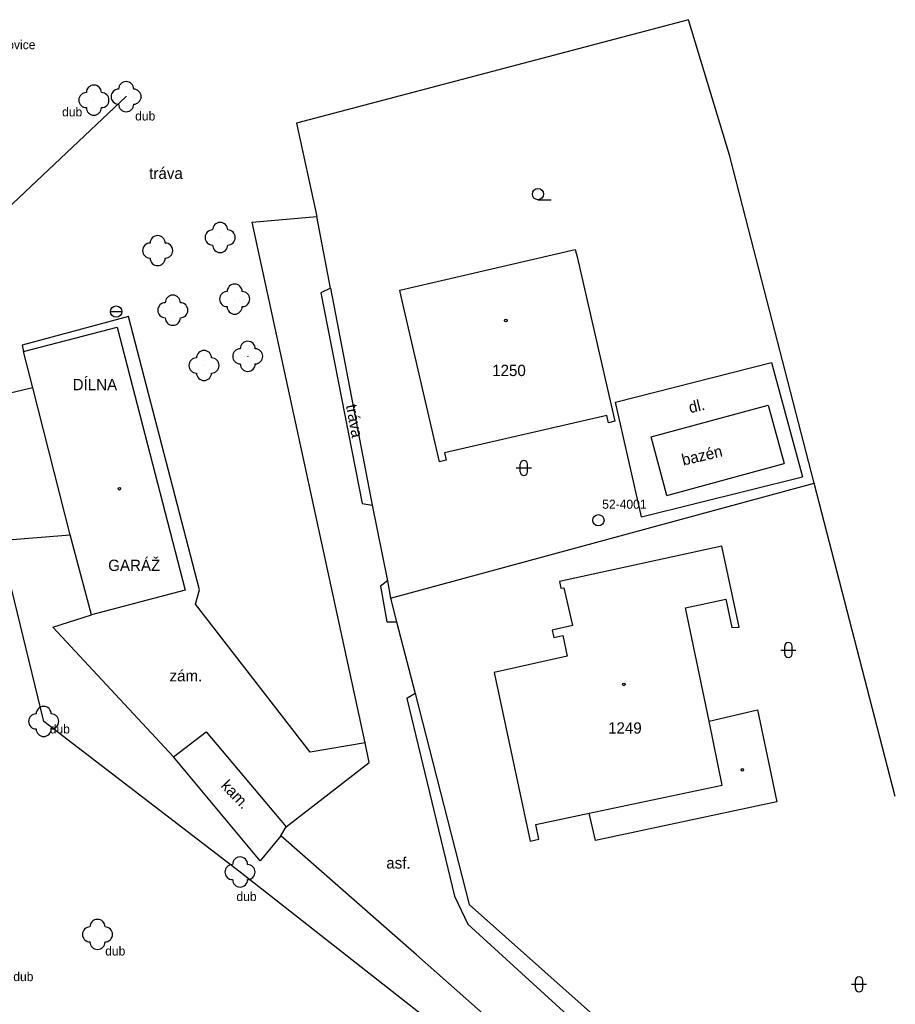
# Model space of a CAD drawing. Extents: x -794191 to -788944, y -1117087 to -1105044.
# Drawn here: x -792191 to -792132.8, y -1110967.2 to -1110901.8 of the extents above; entities that cross this region are included whole.
import ezdxf

# ---------------------------------------------------------------- set-up
doc = ezdxf.new("R2010")
doc.units = 0
for name, color, linetype in [('Doplněk polohopisu', 7, 'Continuous'), ('Doplňkové značky', 7, 'Continuous'), ('Hranice - ploty_ zdi', 7, 'Continuous'), ('Komunikace', 7, 'Continuous'), ('Pomocné popisy', 7, 'Continuous'), ('Popisy budov', 7, 'Continuous'), ('Stavební objekty', 7, 'Continuous'), ('temporary_level_1', 7, 'Continuous'), ('Zeleň', 7, 'Continuous'), ('Značky druhů budov', 7, 'Continuous'), ('Značky druhů pozemků', 7, 'Continuous'), ('Čísla popisná', 7, 'Continuous')]:
    doc.layers.add(name, color=color, linetype=linetype)

msp = doc.modelspace()

# ---------------------------------------------------------------- linework, layer by layer
at = {"layer": 'Doplněk polohopisu'}
for points in [[(-792168.03, -1110949.86), (-792171.67, -1110950.47), (-792179.29, -1110940.65), (-792179.02, -1110939.7), (-792183.73, -1110921.55), (-792190.8, -1110923.44), (-792190.7, -1110923.87)], [(-792173.62, -1110956.03), (-792174.99, -1110957.68), (-792180.75, -1110950.77), (-792188.75, -1110942.17), (-792186.18, -1110941.36)], [(-792180.75, -1110950.77), (-792178.58, -1110949.12), (-792173.27, -1110955.42)]]:
    msp.add_lwpolyline(points, dxfattribs=at)
at = {"layer": 'Doplňkové značky'}
msp.add_line((-792184.926, -1110921.22), (-792184.174, -1110921.22), dxfattribs=at)
msp.add_circle((-792184.55, -1110921.22), 0.375, dxfattribs=at)
at = {"layer": 'Hranice - ploty_ zdi'}
for p, q in [((-792146.58, -1110901.84), (-792172.59, -1110908.71)), ((-792172.59, -1110908.71), (-792171.23, -1110914.91)), ((-792170.32, -1110919.67), (-792171.23, -1110914.91)), ((-792170.32, -1110919.67), (-792167.56, -1110934.07)), ((-792141.29, -1110927.43), (-792140.23, -1110931.31)), ((-792148.01, -1110933.42), (-792140.23, -1110931.31)), ((-792149.69, -1110934.84), (-792139.01, -1110932.18)), ((-792166.35, -1110940.24), (-792138.23, -1110932.6)), ((-792132.85, -1110953.41), (-792138.23, -1110932.6)), ((-792167.56, -1110934.07), (-792166.55, -1110939.1)), ((-792165.94, -1110941.81), (-792164.72, -1110946.58))]:
    msp.add_line(p, q, dxfattribs=at)
for points in [[(-792138.23, -1110932.6), (-792142.77, -1110915.05), (-792143.84, -1110910.9), (-792146.58, -1110901.84)], [(-792149.69, -1110934.84), (-792151.41, -1110927.24), (-792141.07, -1110924.6), (-792139.01, -1110932.18)], [(-792190.08, -1110926.29), (-792195.76, -1110927.61), (-792192.29, -1110936.41), (-792187.61, -1110936.03)], [(-792148.01, -1110933.42), (-792149.06, -1110929.53), (-792141.29, -1110927.43)], [(-792166.55, -1110939.1), (-792166.35, -1110940.24), (-792165.94, -1110941.81)], [(-792164.72, -1110946.58), (-792161.13, -1110960.59), (-792138.64, -1110980.62)]]:
    msp.add_lwpolyline(points, dxfattribs=at)
at = {"layer": 'Komunikace'}
for p, q in [((-792164.62, -1110963.92), (-792173.62, -1110956.03)), ((-792144.04, -1110982.14), (-792164.62, -1110963.92))]:
    msp.add_line(p, q, dxfattribs=at)
for points in [[(-792168.03, -1110949.86), (-792175.53, -1110915.29), (-792171.23, -1110914.91)], [(-792170.32, -1110919.67), (-792170.96, -1110919.98), (-792168.22, -1110933.97), (-792167.56, -1110934.07)], [(-792166.55, -1110939.1), (-792167.02, -1110939.44), (-792166.58, -1110941.81), (-792165.94, -1110941.81)], [(-792164.72, -1110946.58), (-792165.27, -1110946.9), (-792162.1, -1110960.02), (-792161.21, -1110961.88), (-792139.87, -1110981.39), (-792136.93, -1110983.32), (-792133.45, -1110983.35)], [(-792173.62, -1110956.03), (-792173.27, -1110955.42), (-792167.77, -1110951.15), (-792168.03, -1110949.86)]]:
    msp.add_lwpolyline(points, dxfattribs=at)
at = {"layer": 'Stavební objekty'}
for p, q in [((-792190.7, -1110923.87), (-792184.49, -1110922.25)), ((-792184.49, -1110922.25), (-792179.98, -1110939.71)), ((-792186.18, -1110941.36), (-792187.61, -1110936.03)), ((-792179.98, -1110939.71), (-792186.18, -1110941.36))]:
    msp.add_line(p, q, dxfattribs=at)
for points in [[(-792162.77, -1110930.6), (-792162.66, -1110931.09), (-792163.09, -1110931.19), (-792165.64, -1110920.21), (-792165.73, -1110919.79), (-792154.09, -1110917.09), (-792153.97, -1110917.58), (-792151.46, -1110928.5)], [(-792187.61, -1110936.03), (-792190.08, -1110926.29), (-792190.7, -1110923.87)], [(-792151.46, -1110928.5), (-792151.89, -1110928.6), (-792152, -1110928.11), (-792162.77, -1110930.6)], [(-792144.35, -1110936.8), (-792155.13, -1110939.15), (-792155.04, -1110939.59), (-792154.84, -1110939.55), (-792154.28, -1110942.07), (-792155.62, -1110942.37), (-792155.51, -1110942.86), (-792154.92, -1110942.73), (-792154.62, -1110944.09), (-792159.47, -1110945.17), (-792157.09, -1110956.37), (-792156.51, -1110956.25), (-792156.71, -1110955.28), (-792153.16, -1110954.53), (-792144.33, -1110952.65), (-792145.21, -1110948.42), (-792146.78, -1110940.89)], [(-792146.78, -1110940.89), (-792144.1, -1110940.31), (-792143.69, -1110942.2), (-792143.21, -1110942.17), (-792144.35, -1110936.8)], [(-792145.21, -1110948.42), (-792141.99, -1110947.66), (-792140.71, -1110953.76), (-792152.74, -1110956.33), (-792153.16, -1110954.53)]]:
    msp.add_lwpolyline(points, dxfattribs=at)
at = {"layer": 'temporary_level_1'}
for radius in [0.375, 0.0005]:
    msp.add_circle((-792152.55, -1110935.07), radius, dxfattribs=at)
at = {"layer": 'Zeleň'}
for points in [[(-792195.76, -1110927.61), (-792194.2, -1110916.65), (-792183.89, -1110906.95)], [(-792147, -1110981.48), (-792176.33, -1110958.43), (-792189.36, -1110948.43), (-792192.29, -1110936.41)]]:
    msp.add_lwpolyline(points, dxfattribs=at)
for centre in [(-792186.03, -1110907.18), (-792183.89, -1110906.95), (-792177.65, -1110916.3), (-792181.8, -1110917.17), (-792176.69, -1110920.39), (-792180.79, -1110921.13), (-792175.82, -1110924.19), (-792178.72, -1110924.8), (-792189.36, -1110948.43), (-792176.33, -1110958.43), (-792185.79, -1110962.57)]:
    msp.add_circle(centre, 0.0005, dxfattribs=at)
for centre, start, end in [((-792186.03, -1110906.68), 0, 179.99999), ((-792183.89, -1110906.45), 0, 179.99999), ((-792186.53, -1110907.18), 89.99999, 269.99999), ((-792185.53, -1110907.18), 270, 89.99999), ((-792184.39, -1110906.95), 89.99999, 269.99999), ((-792183.39, -1110906.95), 270, 89.99999), ((-792183.89, -1110907.45), 179.99999, 359.99999), ((-792186.03, -1110907.68), 179.99999, 359.99999), ((-792177.65, -1110915.8), 0, 179.99999), ((-792178.15, -1110916.3), 89.99999, 269.99999), ((-792177.15, -1110916.3), 270, 89.99999), ((-792182.3, -1110917.17), 89.99999, 269.99999), ((-792181.8, -1110916.67), 0, 179.99999), ((-792181.3, -1110917.17), 270, 89.99999), ((-792177.65, -1110916.8), 179.99999, 359.99999), ((-792181.8, -1110917.67), 179.99999, 359.99999), ((-792177.19, -1110920.39), 89.99999, 269.99999), ((-792176.69, -1110919.89), 0, 179.99999), ((-792176.19, -1110920.39), 270, 89.99999), ((-792181.29, -1110921.13), 89.99999, 269.99999), ((-792180.79, -1110920.63), 0, 179.99999), ((-792180.29, -1110921.13), 270, 89.99999), ((-792176.69, -1110920.89), 179.99999, 359.99999), ((-792180.79, -1110921.63), 179.99999, 359.99999), ((-792175.82, -1110923.69), 0, 179.99999), ((-792178.72, -1110924.3), 0, 179.99999), ((-792176.32, -1110924.19), 89.99999, 269.99999), ((-792175.32, -1110924.19), 270, 89.99999), ((-792179.22, -1110924.8), 89.99999, 269.99999), ((-792178.22, -1110924.8), 270, 89.99999), ((-792175.82, -1110924.69), 179.99999, 359.99999), ((-792178.72, -1110925.3), 179.99999, 359.99999), ((-792189.36, -1110947.93), 0, 179.99999), ((-792189.86, -1110948.43), 89.99999, 269.99999), ((-792188.86, -1110948.43), 270, 89.99999), ((-792189.36, -1110948.93), 179.99999, 359.99999), ((-792176.33, -1110957.93), 0, 179.99999), ((-792176.83, -1110958.43), 89.99999, 269.99999), ((-792175.83, -1110958.43), 270, 89.99999), ((-792176.33, -1110958.93), 179.99999, 359.99999), ((-792185.79, -1110962.07), 0, 179.99999), ((-792186.29, -1110962.57), 89.99999, 269.99999), ((-792185.29, -1110962.57), 270, 89.99999), ((-792185.79, -1110963.07), 179.99999, 359.99999)]:
    msp.add_arc(centre, 0.5, start, end, dxfattribs=at)
at = {"layer": 'Značky druhů budov'}
for centre in [(-792158.69, -1110921.81), (-792184.34, -1110932.98), (-792150.86, -1110945.97), (-792143, -1110951.64)]:
    msp.add_circle(centre, 0.0875, dxfattribs=at)
at = {"layer": 'Značky druhů pozemků'}
for p, q in [((-792156.56, -1110913.795), (-792155.685, -1110913.795)), ((-792158, -1110931.6), (-792157, -1110931.6)), ((-792157.75, -1110931.85), (-792157.75, -1110931.35)), ((-792157.25, -1110931.85), (-792157.25, -1110931.35)), ((-792140.19, -1110943.94), (-792140.19, -1110943.44)), ((-792139.69, -1110943.94), (-792139.69, -1110943.44)), ((-792140.44, -1110943.69), (-792139.44, -1110943.69)), ((-792135.5, -1110966.13), (-792135.5, -1110965.63)), ((-792135, -1110966.13), (-792135, -1110965.63)), ((-792135.75, -1110965.88), (-792134.75, -1110965.88))]:
    msp.add_line(p, q, dxfattribs=at)
msp.add_circle((-792156.56, -1110913.42), 0.375, dxfattribs=at)
for centre, start, end in [((-792157.5, -1110931.35), 0, 179.99999), ((-792157.5, -1110931.85), 179.99999, 359.99999), ((-792139.94, -1110943.44), 0, 179.99999), ((-792139.94, -1110943.94), 179.99999, 359.99999), ((-792135.25, -1110965.63), 0, 179.99999), ((-792135.25, -1110966.13), 179.99999, 359.99999)]:
    msp.add_arc(centre, 0.25, start, end, dxfattribs=at)

# ---------------------------------------------------------------- texts
at = {"layer": 'Pomocné popisy'}
for s, p in [('tráva', (-792182.36, -1110912.41)), ('zám.', (-792181.01, -1110945.77)), ('asf.', (-792166.63, -1110958.2))]:
    msp.add_text(s, height=0.75, dxfattribs=at).set_placement(p)
for s, rotation, p in [('dl.', 13.39844, (-792146.46, -1110927.97)), ('tráva', 280.4758, (-792169.31, -1110927.45)), ('bazén', 13.39844, (-792146.92, -1110931.45)), ('kam.', 313.58582, (-792177.65, -1110952.74))]:
    msp.add_text(s, height=0.75, rotation=rotation, dxfattribs=at).set_placement(p)
at = {"layer": 'Popisy budov'}
for s, p in [('DÍLNA', (-792187.44, -1110926.44)), ('GARÁŽ', (-792185.08, -1110938.44))]:
    msp.add_text(s, height=0.75, dxfattribs=at).set_placement(p)
at = {"layer": 'temporary_level_1'}
msp.add_text('52-4001', height=0.6, dxfattribs=at).set_placement((-792152.3, -1110934.31))
at = {"layer": 'Zeleň'}
for s, p in [('borovice', (-792192.94, -1110903.8)), ('dub', (-792188.14, -1110908.26)), ('dub', (-792183.29, -1110908.53)), ('dub', (-792188.96, -1110949.23)), ('dub', (-792176.57, -1110960.35)), ('dub', (-792185.28, -1110963.97)), ('dub', (-792191.38, -1110965.67))]:
    msp.add_text(s, height=0.6, dxfattribs=at).set_placement(p)
at = {"layer": 'Čísla popisná'}
for s, p in [('1250', (-792159.6, -1110925.5)), ('1249', (-792151.91, -1110949.24))]:
    msp.add_text(s, height=0.75, dxfattribs=at).set_placement(p)

doc.saveas('drawing.dxf')
